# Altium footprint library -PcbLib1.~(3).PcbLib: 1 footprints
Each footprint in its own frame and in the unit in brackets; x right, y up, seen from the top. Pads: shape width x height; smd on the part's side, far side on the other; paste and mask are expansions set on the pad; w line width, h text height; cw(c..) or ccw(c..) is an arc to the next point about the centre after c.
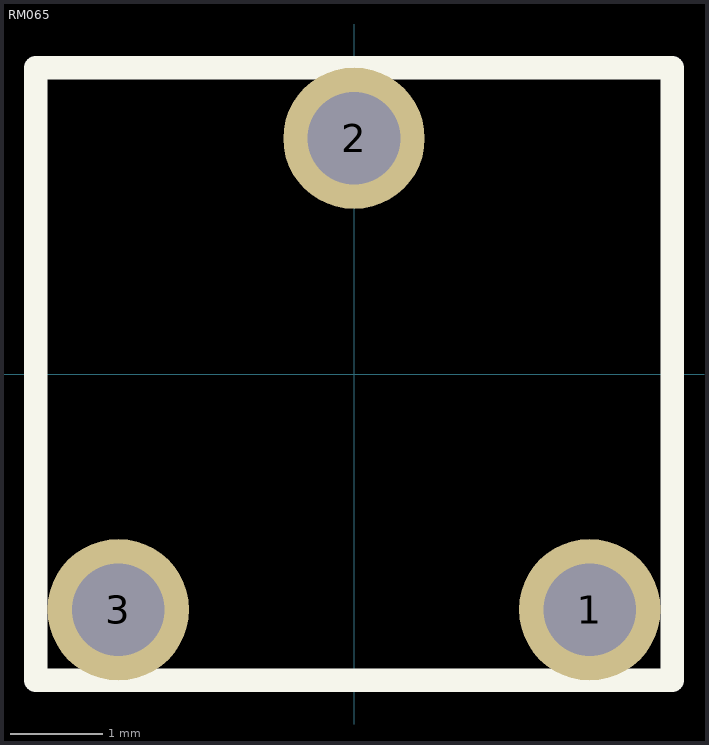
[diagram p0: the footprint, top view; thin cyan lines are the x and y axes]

## RM065 [mil]
pads (3):
  round 60 hole 39.37: 1(100,-100) 2(0,100) 3(-100,-100)
Top Overlay:
  lines w10: -135,-130 135,-130 135,130 -135,130 -135,-130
